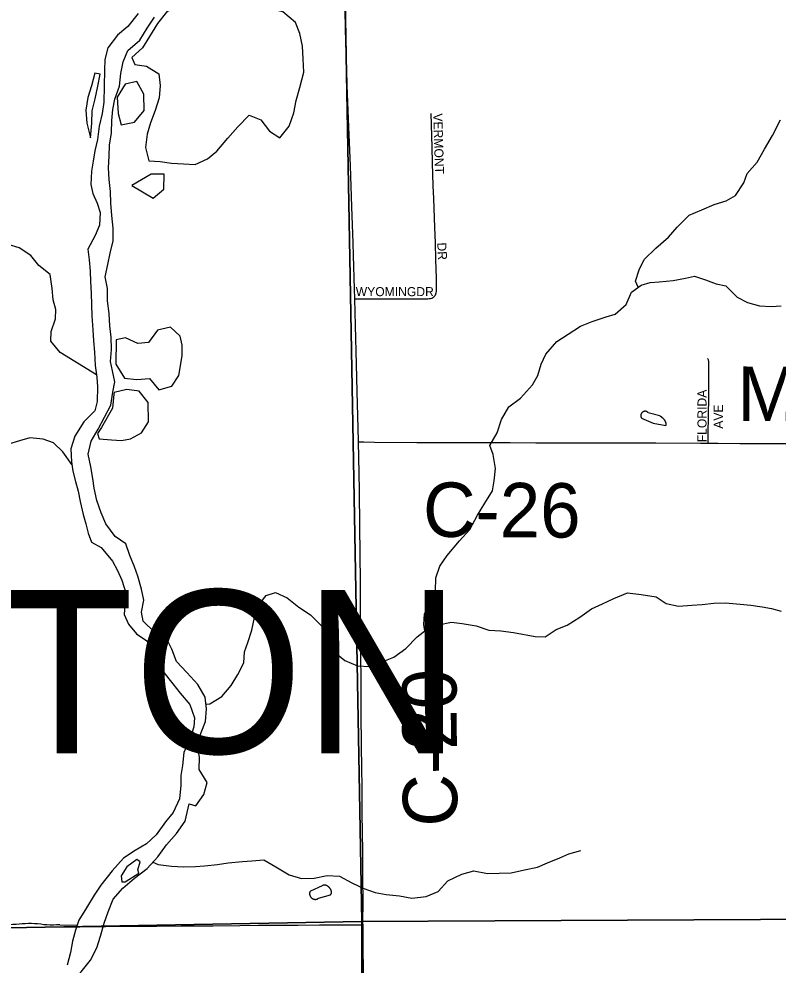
# Model space of a CAD drawing. Extents: x 0 to 1391, y -24 to 440.
# Drawn here: x 400.63 to 416.5, y 308.57 to 328.34 of the extents above; entities that cross this region are included whole.
import ezdxf

# ---------------------------------------------------------------- set-up
doc = ezdxf.new("R2010")
doc.units = 0
for name, color, linetype in [('GM_X_County_Road', 7, 'Continuous'), ('GM_X_County_Road_Text', 7, 'Continuous'), ('GM_X_Minor_Lake', 7, 'Continuous'), ('GM_X_Minor_Lake_Text', 7, 'Continuous'), ('GM_X_Minor_River', 7, 'Continuous'), ('GM_X_Section', 7, 'Continuous'), ('GM_X_Township_Subdivision', 7, 'Continuous'), ('GM_X_Township_Subdivision_Text', 7, 'Continuous'), ('GM_X_Township_Text', 7, 'Continuous')]:
    doc.layers.add(name, color=color, linetype=linetype)

msp = doc.modelspace()

# ---------------------------------------------------------------- linework, layer by layer
at = {"layer": 'GM_X_County_Road'}
for points in [[(407.655, 322.493), (407.647, 322.703), (407.63, 323.399), (407.619, 323.659), (407.594, 324.417), (407.562, 325.274), (407.537, 325.919), (407.525, 326.255), (407.498, 326.948), (407.487, 327.284), (407.467, 327.842), (407.458, 328.165), (407.447, 328.813)], [(407.735, 319.502), (407.734, 319.523), (407.707, 320.554), (407.691, 321.125), (407.671, 321.933), (407.655, 322.493)], [(407.826, 309.416), (407.825, 309.449), (407.826, 309.909), (407.822, 310.381), (407.822, 310.766), (407.819, 311.064), (407.818, 311.225), (407.81, 311.859), (407.806, 312.219), (407.8, 312.766), (407.792, 313.076), (407.793, 313.287), (407.79, 313.697), (407.784, 314.64), (407.781, 314.926), (407.777, 315.373), (407.776, 315.758), (407.77, 316.267), (407.771, 316.565), (407.764, 317.174), (407.759, 317.733), (407.752, 318.479), (407.748, 318.852), (407.735, 319.502)], [(407.735, 319.502), (407.841, 319.502), (408.068, 319.5), (408.953, 319.491), (409.252, 319.493), (409.512, 319.49), (409.984, 319.49), (410.494, 319.491), (410.904, 319.488), (411.438, 319.485), (412.295, 319.484), (412.618, 319.483), (413.289, 319.486), (413.948, 319.485), (414.88, 319.48), (415.038, 319.479)], [(415.038, 319.479), (415.24, 319.478), (415.7, 319.473), (416.681, 319.468), (417.464, 319.464), (418.297, 319.459), (419.676, 319.452), (420.559, 319.449), (421.329, 319.451), (421.913, 319.449), (422.746, 319.442), (422.97, 319.442), (423.193, 319.442), (423.628, 319.441), (424.287, 319.437), (424.97, 319.431), (425.641, 319.424), (426.263, 319.417), (427.341, 319.416)], [(400.308, 309.36), (401.141, 309.368), (401.911, 309.373), (402.446, 309.378), (402.943, 309.383), (403.514, 309.387), (404.024, 309.392), (404.359, 309.392), (404.695, 309.395), (405.254, 309.402), (405.639, 309.406), (406.062, 309.407), (406.471, 309.41), (406.919, 309.414), (407.18, 309.412), (407.59, 309.413), (407.701, 309.415), (407.826, 309.416)], [(407.877, 300.623), (407.878, 300.814), (407.877, 301.249), (407.877, 301.721), (407.875, 302.293), (407.872, 303.026), (407.871, 303.461), (407.871, 304.07), (407.863, 304.542), (407.863, 304.902), (407.858, 305.399), (407.854, 305.722), (407.849, 306.331), (407.846, 306.678), (407.839, 307.076), (407.838, 307.386), (407.842, 307.709), (407.84, 308.256), (407.837, 308.43), (407.829, 308.952), (407.826, 309.416)]]:
    msp.add_lwpolyline(points, dxfattribs=at)
at = {"layer": 'GM_X_Minor_Lake'}
for p, q in [((402.996, 327.534), (403.054, 327.388)), ((402.333, 327.189), (402.219, 327.206)), ((402.685, 326.707), (402.709, 326.366)), ((403.661, 324.786), (403.667, 325.096))]:
    msp.add_line(p, q, dxfattribs=at)
for points in [[(406.504, 326.907), (406.586, 327.231), (406.576, 327.503), (406.558, 327.769), (406.509, 328.035), (406.415, 328.264), (406.153, 328.489), (405.941, 328.539), (405.683, 328.613), (405.441, 328.678), (405.191, 328.699), (404.947, 328.689), (404.757, 328.678), (404.551, 328.644), (404.361, 328.633), (404.171, 328.607), (403.912, 328.597), (403.72, 328.48), (403.533, 328.242), (403.361, 327.973), (403.22, 327.733), (402.996, 327.534)], [(403.054, 327.388), (403.304, 327.353), (403.56, 327.196), (403.586, 326.946), (403.566, 326.689), (403.485, 326.425), (403.382, 326.17), (403.317, 325.929), (403.282, 325.657), (403.353, 325.375), (403.588, 325.363), (403.823, 325.328), (404.074, 325.315), (404.317, 325.302), (404.577, 325.418), (404.77, 325.58), (405.003, 325.848), (405.213, 326.086), (405.445, 326.331), (405.694, 326.235), (405.872, 325.996), (406.09, 325.855), (406.285, 326.101), (406.381, 326.379), (406.431, 326.636), (406.504, 326.907)], [(402.219, 327.206), (402.155, 326.941), (402.076, 326.699), (402.035, 326.434), (402.054, 326.161), (402.129, 325.857)], [(402.129, 325.857), (402.161, 326.16), (402.164, 326.417), (402.228, 326.674), (402.284, 326.932), (402.333, 327.189)], [(403.253, 326.43), (403.248, 326.771), (403.101, 327.032), (402.857, 326.976), (402.685, 326.707)], [(402.709, 326.366), (402.773, 326.13), (403.048, 326.184), (403.253, 326.43)], [(403.667, 325.096), (403.401, 325.094), (402.993, 324.859)], [(402.993, 324.859), (403.438, 324.594), (403.661, 324.786)], [(404.047, 321.298), (404.044, 321.521), (404.002, 321.711), (403.8, 321.897), (403.533, 321.835), (403.346, 321.581), (403.117, 321.556), (402.861, 321.675), (402.67, 321.634), (402.661, 321.129)], [(402.661, 321.129), (402.838, 320.835), (403.096, 320.807), (403.363, 320.831), (403.556, 320.593), (403.831, 320.67), (403.98, 320.894), (404.047, 321.298)], [(402.628, 320.536), (402.621, 320.501), (402.589, 320.21), (402.362, 319.803), (402.275, 319.678), (402.314, 319.566)], [(403.337, 320.323), (403.145, 320.563), (402.887, 320.599), (402.628, 320.536)], [(403.198, 319.691), (403.342, 319.926), (403.337, 320.323)], [(413.788, 320.111), (413.784, 320.115), (413.781, 320.119), (413.777, 320.122), (413.773, 320.125), (413.769, 320.128), (413.765, 320.131), (413.761, 320.133), (413.756, 320.136), (413.752, 320.137), (413.747, 320.139), (413.742, 320.14), (413.737, 320.142), (413.732, 320.142), (413.727, 320.143), (413.722, 320.143), (413.717, 320.143), (413.712, 320.142), (413.707, 320.142), (413.702, 320.141), (413.697, 320.139), (413.692, 320.138), (413.687, 320.136), (413.682, 320.134), (413.678, 320.132), (413.673, 320.129), (413.669, 320.126), (413.665, 320.123), (413.661, 320.12), (413.657, 320.116), (413.654, 320.112), (413.65, 320.108), (413.647, 320.104), (413.644, 320.1), (413.642, 320.096), (413.639, 320.091), (413.637, 320.086), (413.635, 320.082), (413.634, 320.077), (413.633, 320.072), (413.632, 320.067), (413.631, 320.062), (413.631, 320.057), (413.631, 320.052), (413.631, 320.047), (413.631, 320.042), (413.632, 320.037), (413.633, 320.032), (413.635, 320.027), (413.636, 320.022), (413.638, 320.018), (413.641, 320.013), (413.643, 320.009), (413.646, 320.005), (413.649, 320.001)], [(414.03, 320.046), (413.788, 320.111)], [(414.155, 319.846), (414.157, 319.85), (414.159, 319.853), (414.16, 319.857), (414.161, 319.861), (414.162, 319.865), (414.163, 319.869), (414.163, 319.873), (414.163, 319.877), (414.163, 319.882), (414.163, 319.886), (414.162, 319.891), (414.161, 319.896), (414.16, 319.9), (414.158, 319.905), (414.157, 319.91), (414.155, 319.915), (414.153, 319.921), (414.15, 319.926), (414.147, 319.931), (414.144, 319.936), (414.141, 319.941), (414.138, 319.947), (414.134, 319.952), (414.13, 319.957), (414.126, 319.963), (414.122, 319.968), (414.117, 319.973), (414.113, 319.978), (414.108, 319.984), (414.103, 319.989), (414.097, 319.994), (414.092, 319.999), (414.086, 320.004), (414.08, 320.009), (414.074, 320.014), (414.068, 320.019), (414.062, 320.024), (414.056, 320.028), (414.05, 320.033), (414.043, 320.037), (414.036, 320.042), (414.03, 320.046)], [(413.649, 320.001), (413.89, 319.897), (414.155, 319.846)], [(402.314, 319.566), (402.572, 319.546), (402.777, 319.534), (402.968, 319.567), (403.198, 319.691)], [(406.975, 310.229), (406.729, 310.12)], [(407.146, 310.044), (407.149, 310.046), (407.152, 310.05), (407.154, 310.053), (407.157, 310.056), (407.159, 310.06), (407.161, 310.064), (407.162, 310.068), (407.163, 310.072), (407.164, 310.077), (407.165, 310.081), (407.166, 310.086), (407.166, 310.091), (407.166, 310.096), (407.166, 310.101), (407.166, 310.106), (407.165, 310.111), (407.164, 310.116), (407.163, 310.122), (407.161, 310.127), (407.16, 310.132), (407.158, 310.138), (407.155, 310.143), (407.153, 310.148), (407.15, 310.154), (407.148, 310.159), (407.145, 310.164), (407.141, 310.169), (407.138, 310.174), (407.134, 310.179), (407.13, 310.184), (407.126, 310.189), (407.122, 310.193), (407.118, 310.198), (407.114, 310.202), (407.109, 310.206), (407.104, 310.21), (407.1, 310.214), (407.095, 310.218), (407.09, 310.221), (407.085, 310.225), (407.08, 310.228), (407.075, 310.23), (407.069, 310.233), (407.064, 310.235), (407.059, 310.237), (407.054, 310.239), (407.049, 310.241), (407.044, 310.242), (407.038, 310.243), (407.033, 310.244), (407.028, 310.245), (407.023, 310.245), (407.019, 310.245), (407.014, 310.245), (407.009, 310.244), (407.005, 310.244), (407.001, 310.243), (406.996, 310.242), (406.992, 310.24), (406.988, 310.238), (406.985, 310.236), (406.981, 310.234), (406.978, 310.232), (406.975, 310.229)], [(406.729, 310.12), (406.726, 310.117), (406.723, 310.113), (406.721, 310.109), (406.718, 310.104), (406.716, 310.1), (406.714, 310.095), (406.713, 310.091), (406.711, 310.086), (406.71, 310.081), (406.709, 310.076), (406.709, 310.071), (406.709, 310.066), (406.709, 310.06), (406.709, 310.055), (406.71, 310.05), (406.711, 310.045), (406.712, 310.039), (406.713, 310.034), (406.715, 310.029), (406.717, 310.024), (406.719, 310.018), (406.722, 310.013), (406.724, 310.008), (406.727, 310.004), (406.73, 309.999), (406.734, 309.994), (406.738, 309.99), (406.741, 309.985), (406.745, 309.981), (406.75, 309.977), (406.754, 309.974), (406.759, 309.97), (406.763, 309.967), (406.768, 309.964), (406.773, 309.961), (406.778, 309.958), (406.783, 309.956), (406.788, 309.953), (406.794, 309.952), (406.799, 309.95), (406.804, 309.948), (406.81, 309.947), (406.815, 309.947), (406.821, 309.946), (406.826, 309.946), (406.831, 309.946), (406.837, 309.946), (406.842, 309.946), (406.847, 309.947), (406.852, 309.948), (406.857, 309.95), (406.862, 309.951), (406.866, 309.953), (406.871, 309.955), (406.875, 309.958), (406.879, 309.96), (406.883, 309.963), (406.887, 309.966), (406.891, 309.97), (406.894, 309.973)], [(406.894, 309.973), (407.146, 310.044)]]:
    msp.add_lwpolyline(points, dxfattribs=at)
at = {"layer": 'GM_X_Minor_Lake_Text'}
for p, q in [((403.097, 310.781), (402.889, 310.624)), ((403.172, 310.727), (403.097, 310.781)), ((402.889, 310.624), (402.773, 310.436)), ((403.117, 310.561), (403.172, 310.727)), ((403.139, 310.492), (403.117, 310.561)), ((402.773, 310.436), (402.787, 310.315)), ((402.855, 310.314), (403.139, 310.492)), ((402.787, 310.315), (402.855, 310.314))]:
    msp.add_line(p, q, dxfattribs=at)
at = {"layer": 'GM_X_Minor_River'}
msp.add_line((401.492, 309.414), (401.852, 309.407), dxfattribs=at)
for points in [[(403.126, 328.452), (402.909, 328.182), (402.693, 328.004), (402.49, 327.735), (402.433, 327.493), (402.421, 327.273), (402.41, 326.598), (402.376, 326.364), (402.31, 326.099), (402.275, 325.819), (402.218, 325.585), (402.184, 325.366), (402.15, 325.161), (402.138, 324.881), (402.18, 324.691), (402.268, 324.492), (402.333, 324.293), (402.321, 324.028), (402.226, 323.817), (402.077, 323.532), (402.104, 323.304), (402.123, 323.068), (402.134, 322.856), (402.145, 322.613), (402.149, 322.37), (402.16, 322.135), (402.178, 321.846), (402.19, 321.618), (402.216, 321.375), (402.227, 321.102), (402.261, 320.859), (402.28, 320.653), (402.267, 320.35), (402.218, 320.154), (401.994, 319.923), (401.806, 319.622), (401.718, 319.358), (401.736, 319.085), (401.763, 318.895), (401.82, 318.674), (401.87, 318.476), (401.912, 318.255), (401.976, 317.989), (402.034, 317.79), (402.084, 317.6), (402.15, 317.409), (402.353, 317.299), (402.592, 317.014), (402.695, 316.815), (402.783, 316.617), (402.87, 316.35), (402.851, 316.107), (402.832, 315.895), (402.928, 315.696), (403.092, 315.496), (403.31, 315.348), (403.444, 315.149), (403.524, 314.935), (403.635, 314.721), (403.851, 314.451), (404.008, 314.251), (404.209, 314.02), (404.304, 313.738), (404.293, 313.549), (404.205, 313.285), (404.078, 313.014), (404.051, 312.741), (404.017, 312.537), (404.021, 312.332), (403.994, 312.044), (403.859, 311.758), (403.696, 311.564), (403.501, 311.294), (403.3, 311.108), (403.062, 310.968), (402.823, 310.805), (402.583, 310.544), (402.349, 310.245), (402.209, 310.035), (402.044, 309.772), (401.888, 309.51)], [(404.192, 311.942), (404.329, 311.903), (404.497, 312.137), (404.567, 312.386), (404.401, 312.661), (404.411, 312.918), (404.359, 313.184), (404.444, 313.433), (404.536, 313.66), (404.553, 313.925), (404.524, 314.168), (404.373, 314.434), (404.147, 314.686), (403.928, 314.916), (403.831, 315.174), (403.711, 315.41), (403.468, 315.526), (403.234, 315.756), (403.197, 315.945), (403.244, 316.195), (403.2, 316.43), (403.118, 316.696), (403.051, 316.894), (402.953, 317.13), (402.871, 317.373), (402.644, 317.527), (402.448, 317.794), (402.351, 318.022), (402.261, 318.28), (402.209, 318.539), (402.18, 318.736), (402.136, 318.979), (402.084, 319.244), (402.147, 319.517), (402.292, 319.766), (402.423, 320.022), (402.553, 320.271), (402.6, 320.544), (402.639, 320.755), (402.588, 320.991), (402.551, 321.181), (402.567, 321.431), (402.561, 321.688), (402.532, 321.931), (402.518, 322.189), (402.489, 322.447), (402.483, 322.705), (402.439, 322.955), (402.494, 323.212), (402.54, 323.447), (402.603, 323.704), (402.604, 323.969), (402.575, 324.235), (402.554, 324.493), (402.548, 324.735), (402.519, 324.986), (402.505, 325.228), (402.521, 325.471), (402.53, 325.706), (402.57, 325.963), (402.579, 326.22), (402.595, 326.448), (402.642, 326.667), (402.734, 326.932), (402.766, 327.197), (402.813, 327.446), (402.913, 327.68), (403.165, 327.898), (403.318, 328.147), (403.471, 328.38)], [(413.574, 322.733), (413.524, 322.858), (413.594, 323.1), (413.701, 323.311), (413.945, 323.552), (414.213, 323.784), (414.388, 323.987), (414.64, 324.243), (414.907, 324.354), (415.165, 324.466), (415.416, 324.539), (415.607, 324.651), (415.783, 324.915), (415.852, 325.111), (416.066, 325.344), (416.22, 325.616), (416.381, 325.903), (416.55, 326.235)], [(402.254, 320.904), (401.496, 321.374), (401.305, 321.606), (401.31, 321.811), (401.399, 322.074), (401.404, 322.271), (401.348, 322.47), (401.331, 322.706), (401.285, 323.002), (401.048, 323.19), (400.886, 323.399), (400.64, 323.556), (400.407, 323.63)], [(409.121, 315.555), (409.096, 315.689), (409.112, 315.909), (409.227, 316.12), (409.342, 316.384), (409.351, 316.665), (409.429, 316.906), (409.582, 317.132), (409.842, 317.433), (410.056, 317.674), (410.217, 317.976), (410.37, 318.224), (410.531, 318.481), (410.57, 318.693), (410.594, 318.95), (410.543, 319.239), (410.475, 319.429), (410.629, 319.693), (410.721, 319.972), (410.875, 320.236), (411.119, 320.416), (411.371, 320.694), (411.478, 320.89), (411.548, 321.125), (411.648, 321.336), (411.877, 321.599), (412.113, 321.756), (412.372, 321.921), (412.616, 322.017), (412.905, 322.113), (413.095, 322.172), (413.324, 322.375), (413.439, 322.631), (413.637, 322.781), (413.828, 322.833), (414.017, 322.846), (414.306, 322.874), (414.565, 322.925), (414.755, 322.968), (414.982, 322.891), (415.209, 322.805), (415.407, 322.766), (415.648, 322.529), (415.86, 322.413), (416.11, 322.343), (416.353, 322.333), (416.566, 322.346)], [(401.744, 319.028), (401.552, 319.294), (401.36, 319.481), (401.143, 319.562), (400.863, 319.591), (400.65, 319.528), (400.414, 319.458)], [(404.541, 314.022), (404.622, 314.031), (404.873, 314.187), (405.072, 314.413), (405.21, 314.647), (405.333, 314.888), (405.349, 315.116), (405.418, 315.312), (405.503, 315.569), (405.558, 315.834), (405.62, 316.068), (405.804, 316.294), (405.994, 316.36), (406.244, 316.245), (406.486, 316.053), (406.728, 315.892), (406.962, 315.655), (407.158, 315.41), (407.179, 315.153), (407.444, 314.938), (407.709, 314.822), (407.967, 314.812), (408.226, 314.908), (408.469, 315.005), (408.721, 315.185), (408.957, 315.433), (409.148, 315.575), (409.407, 315.679), (409.673, 315.737), (409.901, 315.712), (410.189, 315.664), (410.454, 315.571), (410.704, 315.554), (410.97, 315.521), (411.425, 315.441), (411.63, 315.432), (411.866, 315.581), (412.095, 315.678), (412.354, 315.842), (412.598, 316.015), (412.834, 316.119), (413.07, 316.23), (413.351, 316.349), (413.64, 316.316), (413.951, 316.268), (414.162, 316.13), (414.42, 316.074), (414.701, 316.095), (414.914, 316.108), (415.157, 316.136), (415.4, 316.142), (415.711, 316.116), (415.931, 316.092), (416.166, 316.059), (416.364, 316.02), (416.568, 315.965)], [(401.506, 308.048), (401.696, 308.198), (401.933, 308.43), (402.132, 308.679), (402.262, 308.935), (402.34, 309.177), (402.417, 309.449), (402.502, 309.684), (402.602, 309.948), (402.808, 310.181), (403.052, 310.391), (403.312, 310.594), (403.541, 310.834), (403.717, 311.083), (403.931, 311.323), (404.107, 311.579), (404.192, 311.942)], [(403.433, 310.721), (403.548, 310.675), (403.821, 310.642), (404.071, 310.625), (404.322, 310.63), (404.512, 310.644), (404.785, 310.672), (405.006, 310.708), (405.309, 310.735), (405.499, 310.749), (405.75, 310.769), (406.007, 310.623), (406.28, 310.461), (406.538, 310.383), (406.803, 310.389), (407.077, 310.447), (407.335, 310.429), (407.592, 310.291), (407.842, 310.175), (408.077, 310.089), (408.312, 310.05), (408.586, 310.017), (408.843, 309.969), (409.147, 310.004), (409.399, 310.108), (409.597, 310.334), (409.894, 310.475), (410.145, 310.541), (410.426, 310.486), (410.669, 310.491), (410.919, 310.497), (411.201, 310.562), (411.474, 310.621), (411.68, 310.71), (411.938, 310.814), (412.129, 310.895), (412.38, 310.969)], [(401.888, 309.51), (401.816, 309.306), (401.758, 309.072), (401.716, 308.837), (401.643, 308.573)]]:
    msp.add_lwpolyline(points, dxfattribs=at)
msp.add_spline([(401.492, 309.414), (401.219, 309.411), (400.962, 309.438), (400.446, 309.416), (400.195, 309.413), (399.937, 309.402), (399.743, 309.58), (399.717, 309.846), (399.721, 310.073), (399.718, 310.324), (399.714, 310.59), (399.696, 310.833), (399.708, 311.106), (399.689, 311.311), (399.663, 311.585), (399.614, 311.829), (399.595, 312.08), (399.577, 312.345), (399.581, 312.588), (399.569, 312.786), (399.55, 312.991), (399.554, 313.249), (399.531, 313.675), (399.513, 313.941), (399.396, 314.193), (399.248, 314.446), (399.002, 314.678), (398.753, 314.773), (398.473, 314.823), (398.207, 314.79), (397.934, 314.756), (397.737, 314.775), (397.545, 314.634), (397.308, 314.494), (397.058, 314.551), (396.793, 314.563), (396.558, 314.536), (396.327, 314.335), (396.103, 314.096)], degree=3, dxfattribs=at)
at = {"layer": 'GM_X_Section'}
for points in [[(407.447, 329.121), (407.8, 309.486), (387.556, 309.121), (387.293, 328.839)], [(427.403, 329.248), (427.24, 309.578), (407.8, 309.486), (407.447, 329.121)], [(427.24, 309.578), (427.002, 289.599), (407.817, 289.368), (407.8, 309.486)], [(407.8, 309.486), (407.817, 289.368), (387.942, 289.2), (387.563, 308.758), (387.556, 309.121)]]:
    msp.add_lwpolyline(points, close=True, dxfattribs=at)
at = {"layer": 'GM_X_Township_Subdivision'}
for points in [[(409.305, 322.533), (409.321, 322.546), (409.334, 322.56), (409.344, 322.577), (409.35, 322.595), (409.356, 322.62), (409.359, 322.648), (409.362, 322.704), (409.36, 322.916), (409.349, 323.313), (409.339, 323.66), (409.327, 323.983), (409.304, 324.591), (409.295, 324.852), (409.279, 325.336), (409.272, 325.659), (409.251, 326.366)], [(407.655, 322.493), (407.847, 322.494), (408.804, 322.494), (409.04, 322.492), (409.139, 322.493), (409.181, 322.494), (409.209, 322.496), (409.235, 322.5), (409.261, 322.508), (409.285, 322.519), (409.305, 322.533)], [(415.038, 319.479), (415.041, 319.65), (415.048, 320.072), (415.051, 320.424), (415.051, 320.788), (415.052, 321.124), (415.052, 321.144), (415.051, 321.159), (415.05, 321.175), (415.05, 321.191), (415.048, 321.206), (415.045, 321.218), (415.04, 321.232), (415.032, 321.242), (415.026, 321.249)]]:
    msp.add_lwpolyline(points, dxfattribs=at)

# ---------------------------------------------------------------- texts
at = {"layer": 'GM_X_County_Road_Text'}
for s, rotation, p in [('MILLCREEK', 359.7606, (415.648, 319.943)), ('C-26', 359.6552, (409.077, 317.522)), ('C-20', 90.3429, (409.798, 311.469))]:
    msp.add_text(s, height=1.1364, rotation=rotation, dxfattribs=at).set_placement(p)
at = {"layer": 'GM_X_Township_Subdivision_Text'}
for s, rotation, p in [('VERMONT', 271.6856, (409.293, 326.363)), ('DR', 273.0116, (409.376, 323.664)), ('WYOMING', 0, (407.674, 322.548)), ('DR', 0, (408.94, 322.548)), ('FLORIDA', 90, (415.005, 319.496)), ('AVE', 90, (415.347, 319.779))]:
    msp.add_text(s, height=0.1894, rotation=rotation, dxfattribs=at).set_placement(p)
at = {"layer": 'GM_X_Township_Text'}
msp.add_text('WASHINGTON', height=3.4091, rotation=0, dxfattribs=at).set_placement((378.466, 312.997))

doc.saveas('drawing.dxf')
